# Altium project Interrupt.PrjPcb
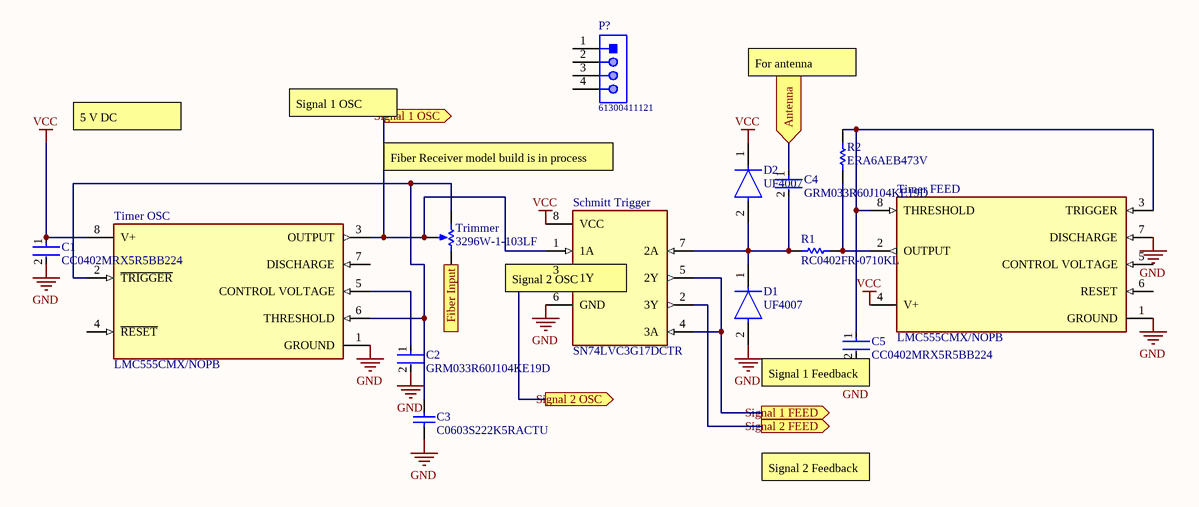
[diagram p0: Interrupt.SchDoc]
1 sheet, 14 parts. Net scope: flat (ports and power ports of the same name join across sheets).
Board file: Interrupt.PcbDoc

## Sheet Interrupt.SchDoc
size A; SheetNumber: 1; SheetTotal: 1

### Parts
C1  CC0402MRX5R5BB224  [FP-CC0402-MFG]
C2  GRM033R60J104KE19D  [FP-GRM033-0_03-MFG]
C3  C0603S222K5RACTU  [CAPC1608X87X35NL15T15]
C4  GRM033R60J104KE19D  [FP-GRM033-0_03-MFG]
C5  CC0402MRX5R5BB224  [FP-CC0402-MFG]
D1  UF4007  [FP-017AH-MFG]
D2  UF4007  [FP-017AH-MFG]
P?  61300411121  [61300411121]
R1  RC0402FR-0710KL  [RESC1005X40X25LL05T10]
R2  ERA6AEB473V  [RESC2013X60X40LL20T25]
Schmitt_Trigger  SN74LVC3G17DCTR  [FP-DCT0008A-MFG]
Timer_FEED  LMC555CMX/NOPB  [FP-D0008A-MFG]
Timer_OSC  LMC555CMX/NOPB  [FP-D0008A-MFG]
Trimmer  3296W-1-103LF  [BOUR-3296W]

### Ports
Antenna (in), Fiber Input (in), Signal 1 FEED (out), Signal 1 OSC (out), Signal 2 FEED (out), Signal 2 OSC (out)

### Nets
GND: C1.2 C2.2 C3.1 C5.2 D1.2(A) Schmitt_Trigger.6(GND) Timer_FEED.1(GROUND) Timer_FEED.7(DISCHARGE) Timer_OSC.1(GROUND)
VCC: C1.1 D2.1(C) Schmitt_Trigger.8(VCC) Timer_FEED.4(V+) Timer_OSC.8(V+)
NetC2_1: C2.1 Timer_OSC.5(CONTROL_VOLTAGE)
NetC3_2: C3.2 Timer_OSC.2(~{TRIGGER}) Timer_OSC.6(THRESHOLD) Trimmer.1(CCW)
NetC4_1: C4.1 ; port Antenna
NetC4_2: C4.2 D1.1(C) D2.2(A) R1.1 Schmitt_Trigger.7(2A)
NetC5_1: C5.1 R2.2 Timer_FEED.3(TRIGGER) Timer_FEED.8(THRESHOLD)
NetR1_2: R1.2 R2.1 Timer_FEED.2(OUTPUT)
NetSchmitt_Trigger_1: Schmitt_Trigger.1(1A) Timer_OSC.3(OUTPUT) Trimmer.2(S) ; port Signal 1 OSC
NetSchmitt_Trigger_2: Schmitt_Trigger.2(3Y) ; port Signal 2 FEED
NetSchmitt_Trigger_3: Schmitt_Trigger.3(1Y) ; port Signal 2 OSC
NetSchmitt_Trigger_4: Schmitt_Trigger.4(3A) Schmitt_Trigger.5(2Y) ; port Signal 1 FEED
NetTrimmer_3: Trimmer.3(CW) ; port Fiber Input

Not connected (* = marked no-connect by the designer): P? 1 2 3 4; Timer_FEED 5(CONTROL_VOLTAGE) 6(RESET); Timer_OSC 4(~{RESET}) 7(DISCHARGE)

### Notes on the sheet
- For antenna
- 5 V DC
- Signal 1 OSC
- Fiber Receiver model build is in process
- (near Schmitt_Trigger) Signal 2 OSC
  Inverted signal output
- (near C5) Signal 1 Feedback
  (inverted)
- Signal 2 Feedback

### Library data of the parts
C1 C5 = CMP-03422-000657-1: CAP CER 0.22UF 6.3V X5R 0402; Manufacturer: YAGEO; Automotive Grade: NA; Material: Ceramic; Value: 220 nF; Tolerance: 0.2; Temperature Coefficient: 30ppm/°C
C2 = CMP-06035-000062-2: 100 nF Chip Multilayer Ceramic Capacitors for General Purpose, 0201, 0.10uF, X5R, 15%, 10%, 6.3V; Capacitance: 100nF
C3 = CMP-2006-03289-1: Manufacturer: Kemet
C4 = CMP-06035-000062-2: Chip Multilayer Ceramic Capacitors for General Purpose, 0201, 0.10uF, X5R, 15%, 10%, 6.3V; Capacitance: 100nF
D1 D2 = CMP-2000-05028-2: DIODE GEN PURP 1KV 1A DO41; Manufacturer: ON Semiconductor; Capacitance: 17pF; Max Surge Forward Current: 30A; Max Repetitive Reverse Voltage: 1000V; Value: 17pF; Max Junction Temp: +150°C; Peak Reverse Current: 10uA
P? = CMP-1502-01064-1: THT Vertical Pin Header WR-PHD, Pitch 2.54 mm, Single Row, 4 pins; Manufacturer: Wurth Elektronik; Withstanding Voltage: 500VAC; Rated Current: 3A; Working Voltage: 250VAC; Pin Number: 4; Gender: Male; Contact Resistance: 20mOhm; Pitch: 2.54mm
R1 = CMP-2002-07353-1: 10Kohm; Manufacturer: Yageo / Phycomp
R2 = CMP-2001-00645-1: Manufacturer: Panasonic
Schmitt_Trigger = CMP-0859-00525-5: IC BUFFER NON-INVERT 5.5V SM8; Manufacturer: Texas Instruments; Logic Function Desc: Non-Inverting; Propagation Delay: 5.1ns; Number Of Inputs: 3; Standoff Height: 0mm; Nominal Supply Current: 10uA; Min Supply Voltage: 1.65V
Timer_FEED Timer_OSC = CMP-04858-000001-1: IC OSC SINGLE TIMER 3MHZ 8-SOIC; Manufacturer: Texas Instruments; Number Of Timers/Counters: 1; Max Supply Voltage: 15V; Standoff Height: 0.11mm; Propagation Delay: 100ns; Nominal Supply Current: 50-150uA; Min Supply Voltage: 1.5V
Trimmer = CMP-1747-00001-1: Square Trimpot(R) Trimming Potentiometer, 10 KOhm, +/- 10%, 0.5 W, -55 to 125 degC, 3-Pin THD, RoHS, Tube; Voltage Rating: 75 V; Resistance: 120 Ohm; Tolerance: 1%; Power Rating: 100 mW; Case\Package: 0603; Type (Resistor): Thick Film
